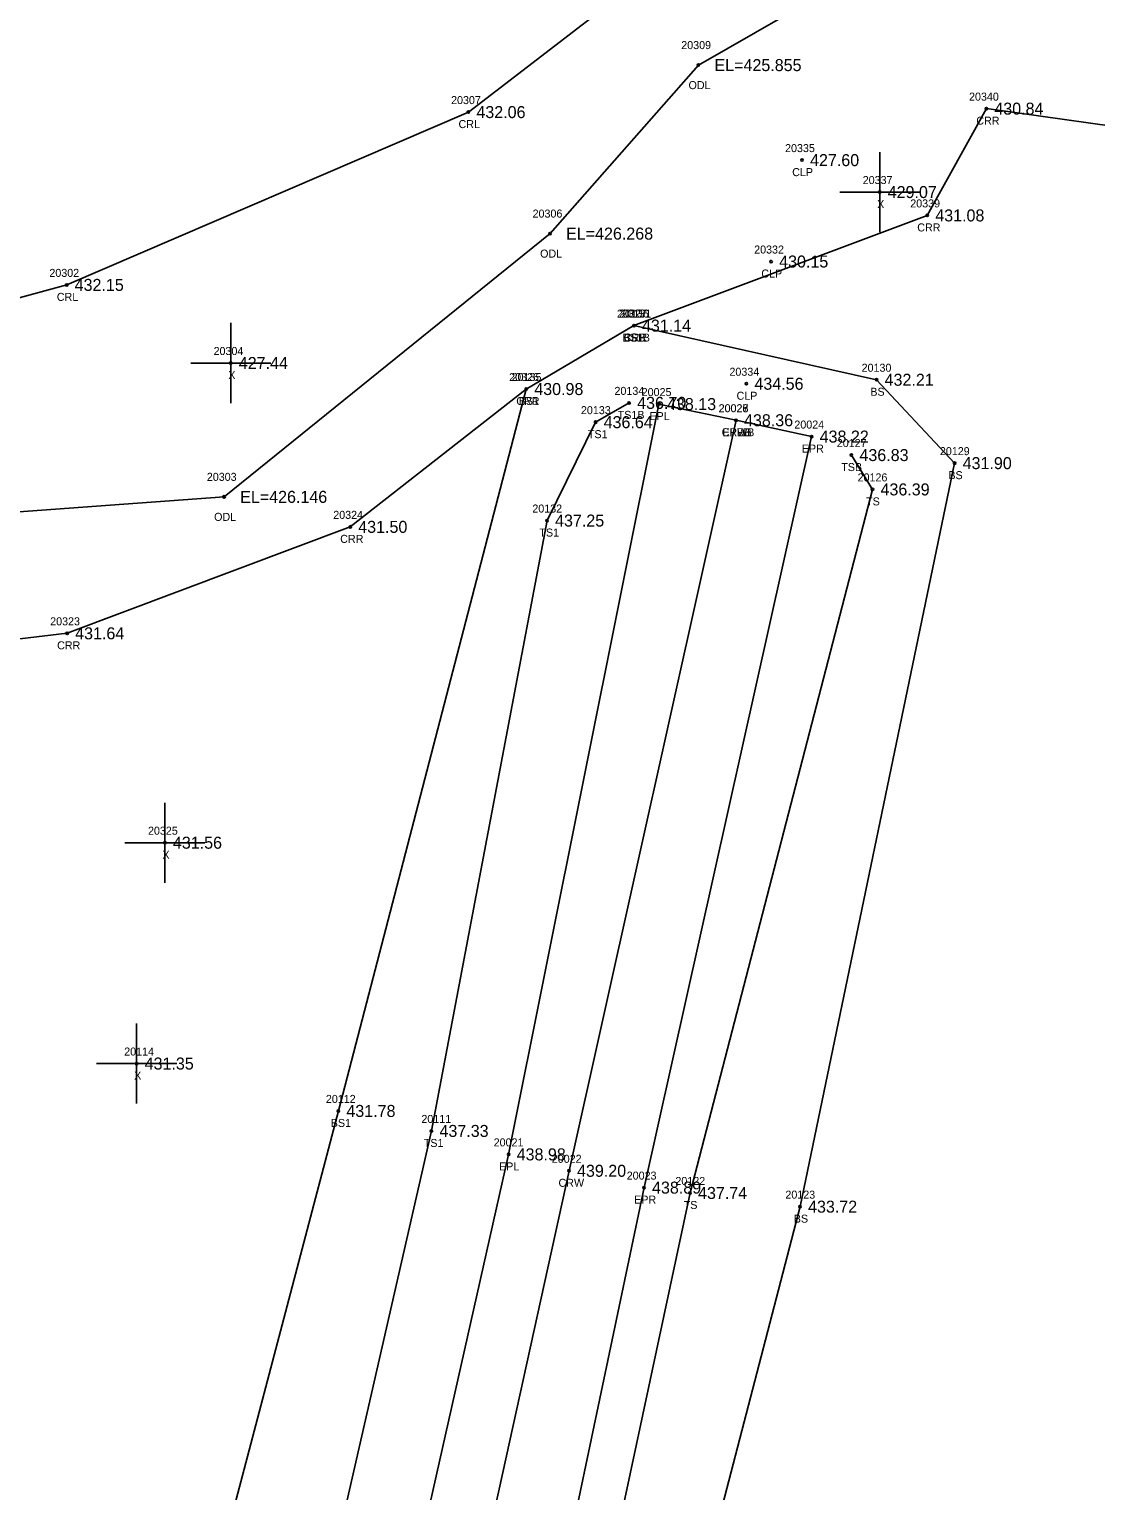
# Model space of a CAD drawing. Extents: x 1755707 to 1756750, y 975854 to 977363.
# Drawn here: x 1756104.5 to 1756237.7, y 976425.4 to 976608 of the extents above; entities that cross this region are included whole.
import ezdxf

# ---------------------------------------------------------------- set-up
doc = ezdxf.new("R2010")
doc.units = 0
for name, color, linetype in [('RD_DTM_BkLn1', 7, 'Continuous'), ('RD_DTM_BkLn2', 7, 'Continuous'), ('RD_DTM_BkLn_txCode', 7, 'Continuous'), ('RD_EX_H2O', 7, 'Continuous'), ('RD_EX_H2O_txCode', 7, 'Continuous'), ('RD_EX_Misc', 7, 'Continuous'), ('RD_EX_Misc_txCode', 7, 'Continuous'), ('RD_EX_Road', 7, 'Continuous'), ('RD_EX_Road_txCode', 7, 'Continuous'), ('RD_EX_TX_H2O_ELEV', 7, 'Continuous'), ('RD_EX_TX_Misc_ELEV', 7, 'Continuous'), ('RD_EX_TX_Road_ELEV', 7, 'Continuous'), ('RD_HC_Survey_ELEV', 7, 'Continuous'), ('RD_HC_Survey_txCode', 7, 'Continuous'), ('RD_SMD_Locator', 7, 'Continuous')]:
    doc.layers.add(name, color=color, linetype=linetype)

msp = doc.modelspace()

# ---------------------------------------------------------------- linework, layer by layer
at = {"layer": 'RD_DTM_BkLn1'}
msp.add_lwpolyline([(1756046.01, 975873.44), (1756066.9, 975971.26), (1756086.38, 976067.89), (1756106.72, 976164.82), (1756129.4, 976267.02), (1756150.88, 976369.58), (1756171.91, 976465.4), (1756192.77, 976559.17)], dxfattribs=at)
at = {"layer": 'RD_DTM_BkLn2'}
for points in [[(1756122.13, 976343.84), (1756117.48, 976354.45), (1756118.32, 976378.77), (1756143.1, 976472.88), (1756166.57, 976563.07), (1756180.02, 976571)], [(1756187.82, 976411.13), (1756200.77, 976460.92), (1756220.08, 976553.81), (1756210.33, 976564.23), (1756180.02, 976571)], [(1756033.66, 975875.52), (1756053.42, 975974.8), (1756049.94, 976015.39), (1756032.6, 976091.06), (1756047.31, 976093.5), (1756074.57, 976074.24), (1756094.56, 976168.06), (1756114.78, 976271.24), (1756126.93, 976314.79), (1756122.13, 976343.84), (1756132.72, 976373.93), (1756154.73, 976470.38), (1756169.17, 976546.64), (1756175.23, 976558.93), (1756179.42, 976561.34)], [(1756161.68, 976320.47), (1756158.89, 976323.91), (1756166.16, 976364.76), (1756187.03, 976462.63), (1756209.82, 976550.53), (1756207.19, 976554.82)]]:
    msp.add_lwpolyline(points, dxfattribs=at)
at = {"layer": 'RD_EX_H2O'}
for points in [[(1755737.32, 976440.59), (1755791.96, 976465.24), (1755883.28, 976455.13), (1755971.27, 976482.19), (1756023.59, 976552.72), (1756109.16, 976576.08), (1756159.34, 976597.67), (1756188.28, 976619.95), (1756188.72, 976628.61)], [(1755742.06, 976428.66), (1755806.09, 976451.93), (1755887.6, 976439.2), (1755982.53, 976463.01), (1756033.69, 976542.66), (1756128.83, 976549.6), (1756169.54, 976582.49), (1756188.08, 976603.54), (1756206.03, 976613.84), (1756222.85, 976613.36), (1756242.15, 976615.93), (1756317.48, 976609.64), (1756394.89, 976590.11), (1756422.33, 976593.66), (1756518.23, 976582.93), (1756609.24, 976524.24), (1756704.51, 976490.62)], [(1755755.31, 976405), (1755806.36, 976424.52), (1755883.37, 976426.21), (1755989.26, 976449.51), (1756040.99, 976524.41), (1756109.22, 976532.55), (1756144.58, 976545.85), (1756166.57, 976563.07), (1756180.02, 976571), (1756216.66, 976584.76), (1756224.04, 976598.1), (1756313.82, 976585.45), (1756418.42, 976576.49), (1756511.71, 976558.86), (1756604.42, 976511.73), (1756702.67, 976481.09)]]:
    msp.add_lwpolyline(points, dxfattribs=at)
at = {"layer": 'RD_EX_Misc'}
for p, q in [((1756210.72, 976582.68), (1756210.72, 976592.68)), ((1756205.72, 976587.68), (1756215.72, 976587.68)), ((1756129.66, 976561.32), (1756129.66, 976571.32)), ((1756124.66, 976566.32), (1756134.66, 976566.32)), ((1756121.43, 976501.39), (1756121.43, 976511.39)), ((1756116.43, 976506.39), (1756126.43, 976506.39)), ((1756117.9, 976473.8), (1756117.9, 976483.8)), ((1756112.9, 976478.8), (1756122.9, 976478.8))]:
    msp.add_line(p, q, dxfattribs=at)
at = {"layer": 'RD_EX_Road'}
for points in [[(1756035.19, 975875.88), (1756056.24, 975973.07), (1756076.6, 976069.51), (1756097.1, 976167.18), (1756119.62, 976269.35), (1756142.72, 976371.31), (1756164.37, 976467.45), (1756183.15, 976561.19), (1756192.77, 976559.17)], [(1756056.66, 975870.37), (1756077.66, 975967.46), (1756097.63, 976065.09), (1756118.05, 976161.7), (1756139.04, 976265.41), (1756152.93, 976328.23), (1756161.13, 976367.36), (1756181.28, 976463.3), (1756202.22, 976557.13), (1756192.77, 976559.17)]]:
    msp.add_lwpolyline(points, dxfattribs=at)
at = {"layer": 'RD_SMD_Locator'}
for centre in [(1756188.08, 976603.54), (1756224.04, 976598.1), (1756159.34, 976597.67), (1756201.02, 976591.67), (1756210.72, 976587.68), (1756216.66, 976584.76), (1756169.54, 976582.49), (1756197.16, 976579), (1756109.16, 976576.08), (1756180.02, 976571), (1756180.02, 976571), (1756180.02, 976571), (1756129.66, 976566.32), (1756194.07, 976563.73), (1756210.33, 976564.23), (1756166.57, 976563.07), (1756166.57, 976563.07), (1756179.42, 976561.34), (1756183.15, 976561.19), (1756175.23, 976558.93), (1756192.77, 976559.17), (1756192.77, 976559.17), (1756192.77, 976559.17), (1756202.22, 976557.13), (1756207.19, 976554.82), (1756220.08, 976553.81), (1756128.83, 976549.6), (1756209.82, 976550.53), (1756144.58, 976545.85), (1756169.17, 976546.64), (1756109.22, 976532.55), (1756121.43, 976506.39), (1756117.9, 976478.8), (1756143.1, 976472.88), (1756154.73, 976470.38), (1756164.37, 976467.45), (1756171.91, 976465.4), (1756181.28, 976463.3), (1756187.03, 976462.63), (1756200.77, 976460.92)]:
    msp.add_circle(centre, 0.15, dxfattribs=at)

# ---------------------------------------------------------------- texts
at = {"layer": 'RD_DTM_BkLn_txCode'}
for s, p in [('20136', (1756178.16, 976572)), ('20131', (1756178.46, 976572)), ('BS1B', (1756178.6, 976569)), ('BSB', (1756178.76, 976569)), ('20130', (1756208.46, 976565.23)), ('20135', (1756164.74, 976564.07)), ('BS1', (1756165.63, 976561.07)), ('20134', (1756177.59, 976562.34)), ('BS', (1756209.55, 976562.23)), ('20133', (1756173.4, 976559.93)), ('TS1B', (1756177.99, 976559.34)), ('TS1', (1756174.27, 976556.93)), ('20127', (1756205.36, 976555.82)), ('20129', (1756218.24, 976554.81)), ('TSB', (1756205.92, 976552.82)), ('20126', (1756207.96, 976551.53)), ('BS', (1756219.3, 976551.81)), ('TS', (1756209.02, 976548.53)), ('20132', (1756167.33, 976547.64)), ('TS1', (1756168.21, 976544.64)), ('20112', (1756141.54, 976473.88)), ('20111', (1756153.47, 976471.38)), ('BS1', (1756142.15, 976470.88)), ('TS1', (1756153.77, 976468.38)), ('20122', (1756185.2, 976463.63)), ('TS', (1756186.24, 976460.63)), ('20123', (1756198.94, 976461.92)), ('BS', (1756199.99, 976458.92))]:
    msp.add_text(s, height=1, dxfattribs=at).set_placement(p)
at = {"layer": 'RD_EX_H2O_txCode'}
for s, p in [('20309', (1756185.93, 976605.54)), ('ODL', (1756186.84, 976600.54)), ('20340', (1756221.88, 976599.1)), ('20307', (1756157.18, 976598.67)), ('CRL', (1756158.11, 976595.67)), ('CRR', (1756222.79, 976596.1)), ('20306', (1756167.36, 976584.49)), ('20339', (1756214.54, 976585.76)), ('CRR', (1756215.41, 976582.76)), ('ODL', (1756168.3, 976579.49)), ('20302', (1756107, 976577.08)), ('CRL', (1756107.93, 976574.08)), ('20327', (1756177.9, 976572)), ('CRR', (1756178.76, 976569)), ('20326', (1756164.43, 976564.07)), ('CRR', (1756165.32, 976561.07)), ('20303', (1756126.67, 976551.6)), ('ODL', (1756127.58, 976546.6)), ('20324', (1756142.46, 976546.85)), ('CRR', (1756143.33, 976543.85)), ('20323', (1756107.1, 976533.55)), ('CRR', (1756107.97, 976530.55))]:
    msp.add_text(s, height=1, dxfattribs=at).set_placement(p)
at = {"layer": 'RD_EX_Misc_txCode'}
for s, p in [('20337', (1756208.6, 976588.68)), ('X', (1756210.4, 976585.68)), ('20304', (1756127.51, 976567.32)), ('X', (1756129.35, 976564.32)), ('20325', (1756119.32, 976507.39)), ('X', (1756121.12, 976504.39)), ('20114', (1756116.35, 976479.8)), ('X', (1756117.59, 976476.8))]:
    msp.add_text(s, height=1, dxfattribs=at).set_placement(p)
at = {"layer": 'RD_EX_Road_txCode'}
for s, p in [('20025', (1756180.99, 976562.19)), ('EPL', (1756181.95, 976559.19)), ('20026', (1756190.59, 976560.17)), ('20027', (1756190.61, 976560.17)), ('EPRB', (1756191.07, 976557.17)), ('EPLB', (1756191.09, 976557.17)), ('20024', (1756200.06, 976558.13)), ('EPR', (1756200.99, 976555.13)), ('20021', (1756162.5, 976468.45)), ('EPL', (1756163.17, 976465.45)), ('20023', (1756179.12, 976464.3)), ('EPR', (1756180.05, 976461.3))]:
    msp.add_text(s, height=1, dxfattribs=at).set_placement(p)
at = {"layer": 'RD_EX_TX_H2O_ELEV'}
for s, p in [('EL=425.855', (1756190.08, 976602.79)), ('432.06', (1756160.34, 976596.92)), ('430.84', (1756225.04, 976597.35)), ('431.08', (1756217.66, 976584.01)), ('EL=426.268', (1756171.54, 976581.74)), ('432.15', (1756110.16, 976575.33)), ('431.14', (1756181.02, 976570.25)), ('430.98', (1756167.57, 976562.32)), ('EL=426.146', (1756130.83, 976548.85)), ('431.50', (1756145.58, 976545.1)), ('431.64', (1756110.22, 976531.8))]:
    msp.add_text(s, height=1.5, dxfattribs=at).set_placement(p)
at = {"layer": 'RD_EX_TX_Misc_ELEV'}
for s, p in [('429.07', (1756211.72, 976586.93)), ('431.14', (1756181.02, 976570.25)), ('431.14', (1756181.02, 976570.25)), ('427.44', (1756130.66, 976565.57)), ('430.98', (1756167.57, 976562.32)), ('432.21', (1756211.33, 976563.48)), ('436.70', (1756180.42, 976560.59)), ('436.64', (1756176.23, 976558.18)), ('436.83', (1756208.19, 976554.07)), ('431.90', (1756221.08, 976553.06)), ('436.39', (1756210.82, 976549.78)), ('437.25', (1756170.17, 976545.89)), ('431.56', (1756122.43, 976505.64)), ('431.35', (1756118.9, 976478.05)), ('431.78', (1756144.1, 976472.13)), ('437.33', (1756155.73, 976469.63)), ('437.74', (1756188.03, 976461.88)), ('433.72', (1756201.77, 976460.17))]:
    msp.add_text(s, height=1.5, dxfattribs=at).set_placement(p)
at = {"layer": 'RD_EX_TX_Road_ELEV'}
for s, p in [('438.13', (1756184.15, 976560.44)), ('438.36', (1756193.77, 976558.42)), ('438.36', (1756193.77, 976558.42)), ('438.22', (1756203.22, 976556.38)), ('438.98', (1756165.37, 976466.7)), ('438.89', (1756182.28, 976462.55))]:
    msp.add_text(s, height=1.5, dxfattribs=at).set_placement(p)
at = {"layer": 'RD_HC_Survey_ELEV'}
for s, p in [('427.60', (1756202.02, 976590.92)), ('430.15', (1756198.16, 976578.25)), ('434.56', (1756195.07, 976562.98)), ('438.36', (1756193.77, 976558.42)), ('439.20', (1756172.91, 976464.65))]:
    msp.add_text(s, height=1.5, dxfattribs=at).set_placement(p)
at = {"layer": 'RD_HC_Survey_txCode'}
for s, p in [('20335', (1756198.9, 976592.67)), ('CLP', (1756199.79, 976589.67)), ('20332', (1756195.04, 976580)), ('CLP', (1756195.93, 976577)), ('20334', (1756191.95, 976564.73)), ('CLP', (1756192.84, 976561.73)), ('20028', (1756190.61, 976560.17)), ('CRWB', (1756190.98, 976557.17)), ('20022', (1756169.76, 976466.4)), ('CRW', (1756170.6, 976463.4))]:
    msp.add_text(s, height=1, dxfattribs=at).set_placement(p)

doc.saveas('drawing.dxf')
